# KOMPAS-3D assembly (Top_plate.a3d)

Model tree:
1. X Axis
2. Y Axis
3. Z Axis
4. Origin
5. Linear Pattern:1  (labels: Instance ( 2, 1 );; Instance ( 3, 1 );; Instance ( 4, 1 );; Instance ( 5, 1 );)
     Included Angle = 90; N 2 = 1; Spacing 2 = 10; Orientation = 1

Expressions: TP_W+(2*Delta); TP_W+(2*Delta)-100
Referenced files in C:\Work\01 К О М П А С\Модели примеры\2009_04_For_Poland_AXAPACK\My sample\Box_sample\: skrzynia1.a3d|NT, skrzynia1.a3d|L, skrzynia1.a3d|W, skrzynia1.a3d|Delta, Top_plate.m3d, rail4.m3d
Referenced files in C:\Work\01 К О М П А С\Модели примеры\2009_04_For_Poland_AXAPACK\My sample\: skrzynia1.a3d
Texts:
  Three Point Plane
  Plane at Angle
  Line and Point Plane
  Axis through Two Vertices
  Axis of Feature
  Axis of Conical Surface
  Axis through Edge
  Trim by Surface
  Trim by Sketch
  Intersection Axis of Two Planes
  Two Line Plane
  Line and Face Plane
  Pattern by Sample
  Point in CM
  Feature with No History
  Linear Dimension from Line to Point
  Surface Finish Symbol
  Geometric Tolerance Symbol
  Leader #1
  Leader #2
  Leader #3
  Shape Deviations and Datum
  Node point number
  Mark of coordination axis
  Node point designation
  Mark/Reference designation with leader
  Mark/reference designation on line
  Mark/Reference designation without leader
  LR4
  Instance ( 2, 1 );
  Instance ( 3, 1 );
  Instance ( 4, 1 );
  Instance ( 5, 1 );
